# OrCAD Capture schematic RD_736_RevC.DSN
size Custom; title: DER-736_RevC; rev: A
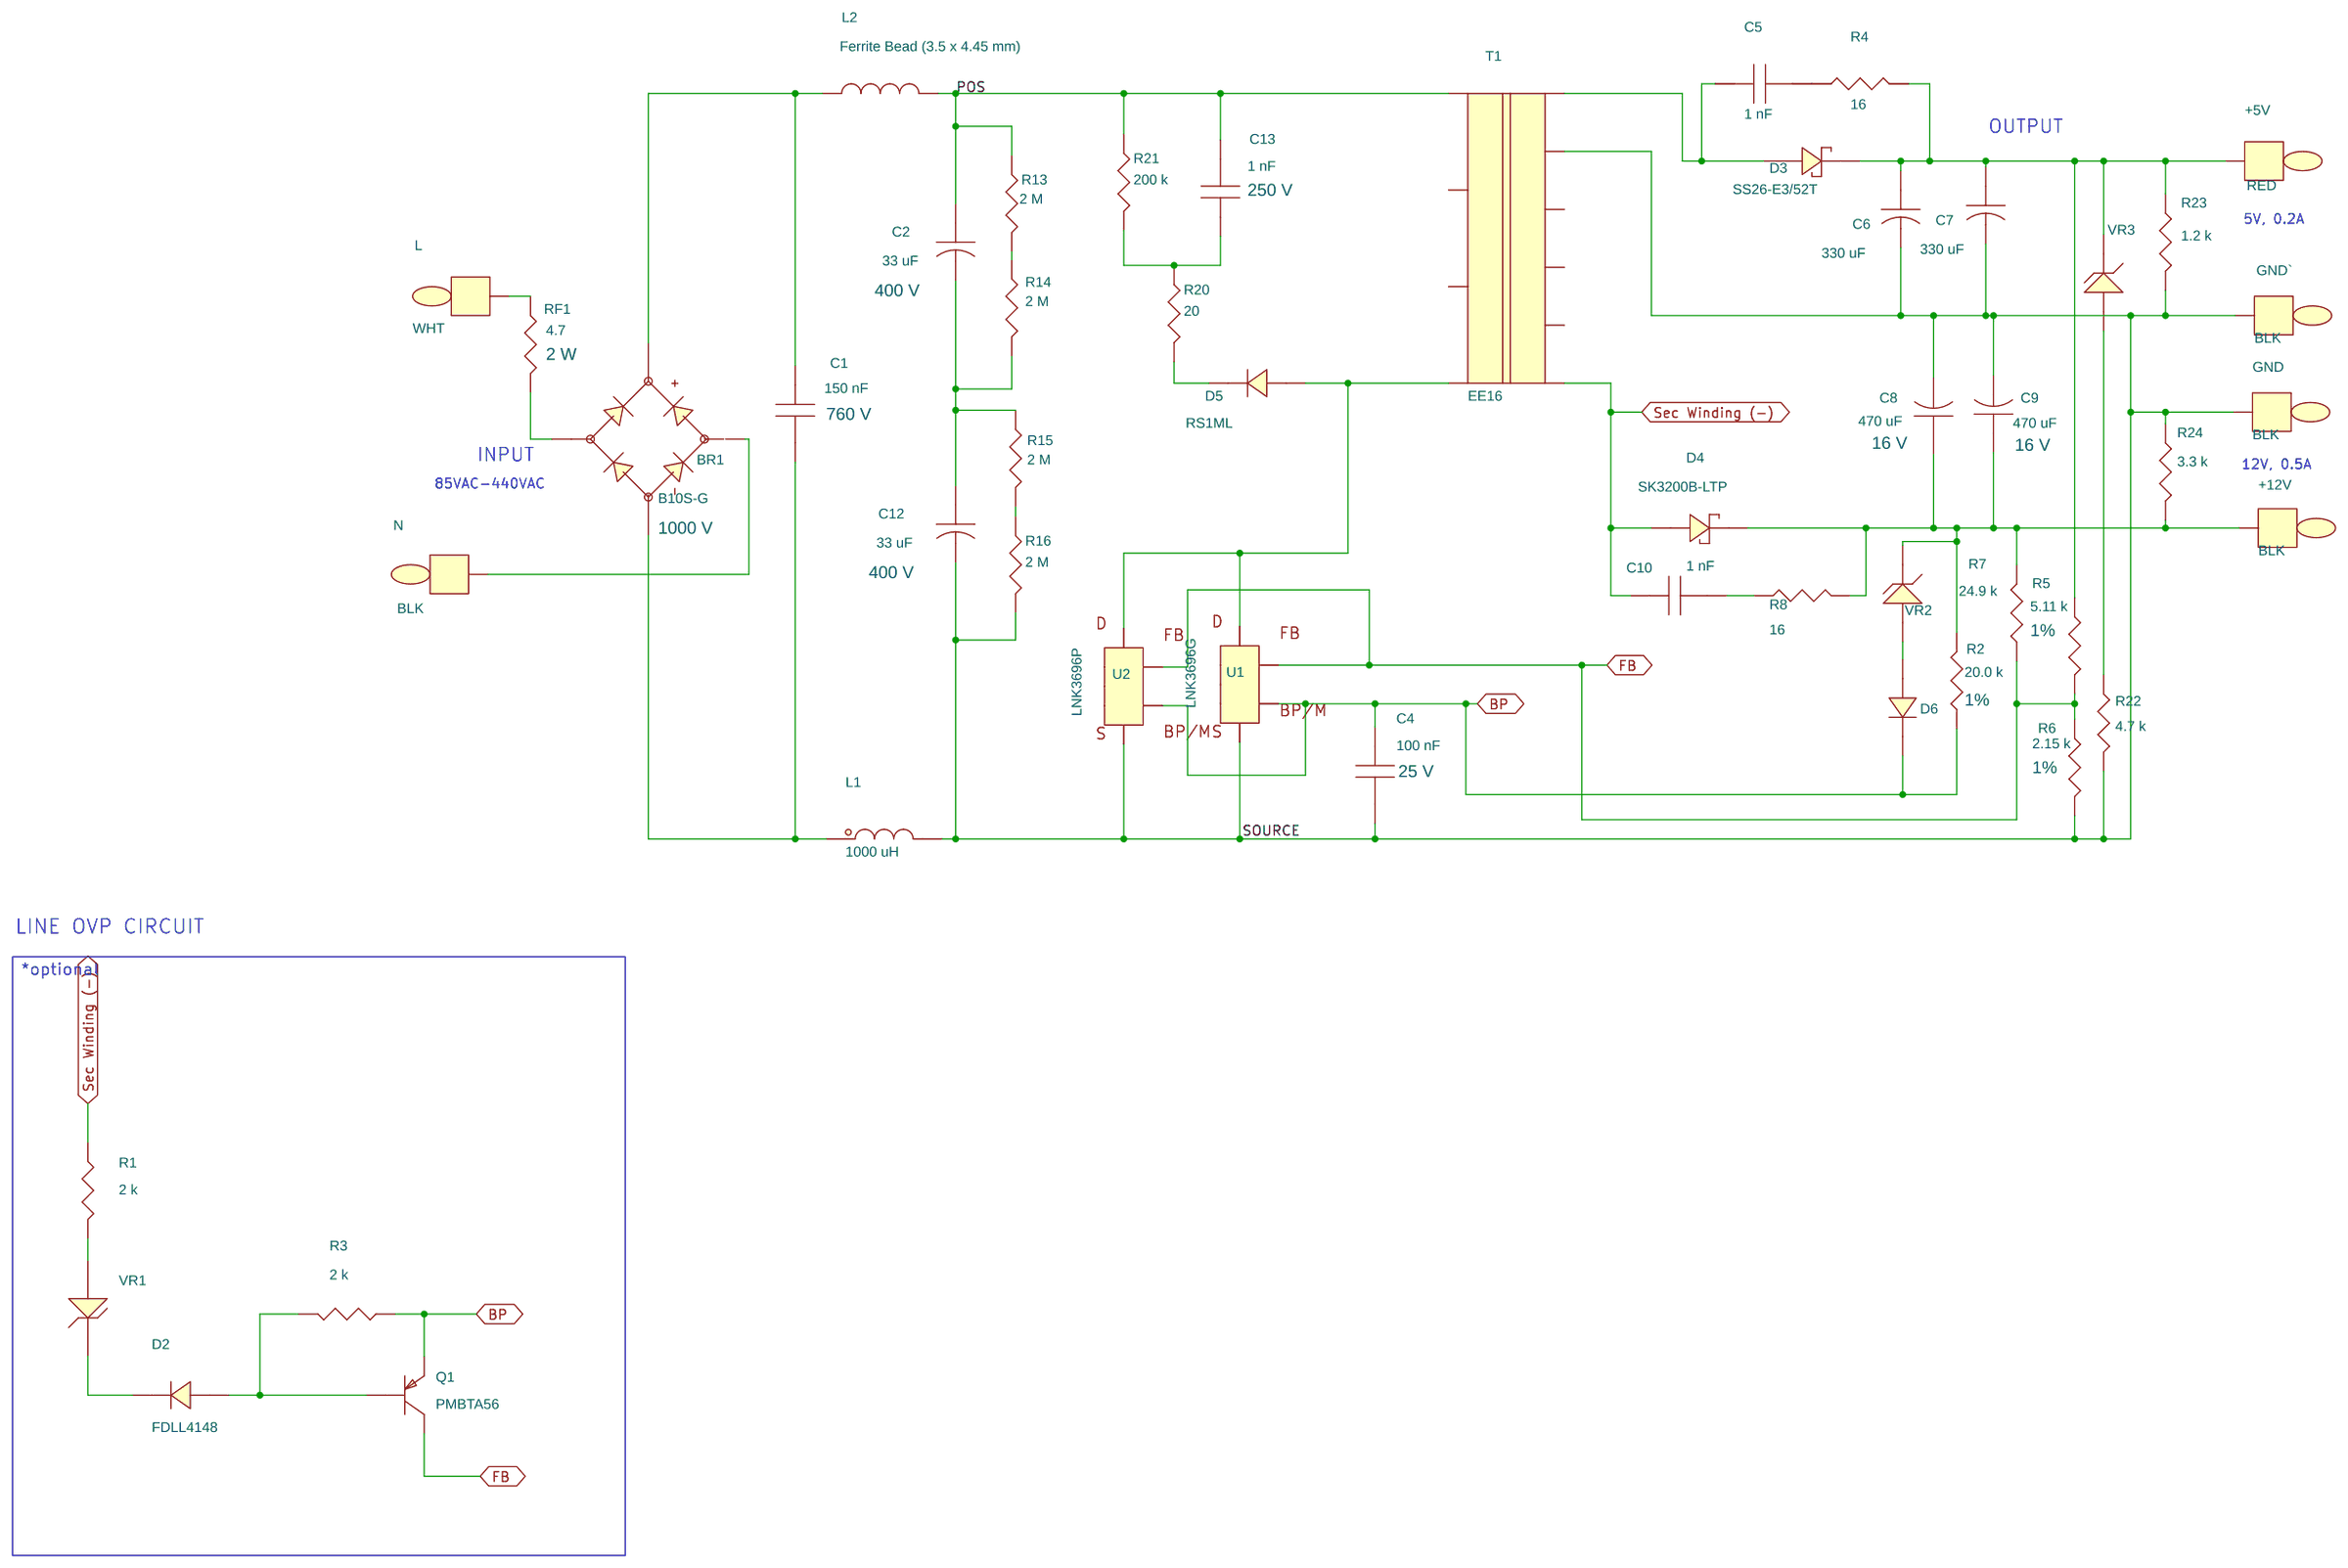
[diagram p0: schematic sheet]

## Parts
+5V  RED  [pitpkeystone100x100]
+12V  BLK  [pitpkeystone100x100]
BR1  B10S-G  [pismsoic4]
C1  150 nF  [pi_np_caprad709x276ls590d050]
C2  33 uF  [pipolcapclyd500ls200040]
C4  100 nF  [pismc1206]
C5  1 nF  [pismc0805]
C6  330 uF  [pipolcapclyd320ls140030]
C7  330 uF  [pipolcapclyd320ls140030]
C8  470 uF  [pipolcapcyld400ls200040]
C9  470 uF  [pipolcapcyld400ls200040]
C10  1 nF  [pismc0805]
C12  33 uF  [pipolcapclyd500ls200040]
C13  1 nF  [pismc0805]
D2  FDLL4148  [pismdminimelf]
D3  SS26-E3/52T  [pismdo214aa12]
D4  SK3200B-LTP  [pismsmb]
D5  RS1ML  [pi_sm_sod-123_12]
D6  FDLL4148  [pismdminimelf]
GND  BLK  [pitpkeystone100x100]
GND`  BLK  [pitpkeystone100x100]
L  WHT  [pitpkeystone125x125]
L1  1000 uH  [pi_choke_RLB9012_D2]
L2  Ferrite Bead (3.5 x 4.45 mm)  [pi12wresd180ls675d040]
N  BLK  [pitpkeystone125x125]
Q1  PMBTA56  [pismsot23123_1]
R1  2 k  [pismr1206]
R2  20.0 k  [pismr1206]
R3  2 k  [pismr0805]
R4  16  [pismr0805]
R5  5.11 k  [pismr0805]
R6  2.15 k  [pismr0603]
R7  24.9 k  [pismr0805]
R8  16  [pismr0805]
R13  2 M  [pismr1206]
R14  2 M  [pismr1206]
R15  2 M  [pismr1206]
R16  2 M  [pismr1206]
R20  20  [pismr1206]
R21  200 k  [pismr1206]
R22  4.7 k  [pismr0805]
R23  1.2 k  [pismr0805]
R24  3.3 k  [pismr0805]
RF1  4.7  [pi_2w_vresd145ls150d040]
T1  EE16  [pibobbinee1610p4x6]
U1  LNK3696G  [piicsmd8cshort5678]
U2  LNK3696P  [piicdip8cshort5678]
VR1  MMSZ5267BT1G  [pi_sm_sod-123_12]
VR2  MMSZ5242B-7-F  [pi_sm_sod-123_12]
VR3  MMSZ5234B-7-F  [pi_sm_sod-123_12]

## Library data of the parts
+5V = TESTPOINT: Part Number: 35-00080-00
+12V GND GND` = TESTPOINT: Part Number: 35-00079-00
BR1 = DIODE_BRIDGE_~~+-: ALT_SYMBOLS: pi_sm_soic4_slot; Disp_Voltage: 1000 V; FPLIST: pismsoic4,pi_sm_soic4_slot; Part Number: 15-00818-00
C1 = CAP_NP: Disp_Voltage: 760 V; Part Number: 20-01058-00; Voltage: 760 V
C2 C12 = CAP_POL: ALT_SYMBOLS: pipolcapclyd500ls200040800lh; COMPGROUP: 1; Disp_Voltage: 400 V; FPLIST: pipolcapclyd500ls200040,pipolcapclyd500ls200040800lh; PCB Editor PCBFP: pipolcapclyd320ls140030; Part Number: 20-00888-00; Voltage: 400 V
C4 = CAP_NP: Disp_Voltage: 25 V; Part Number: 20-08743-00; Voltage: 25 V
C5 = CAP_NP: COMPGROUP: 2; Disp_Voltage: 50 V; Part Number: 20-08750-00; Voltage: 50 V
C6 C7 = CAP_POL: ALT_SYMBOLS: pipolcapclyd320ls140030430h; COMPGROUP: 2; Disp_Voltage: 16 V; FPLIST: pipolcapclyd320ls140030,pipolcapclyd320ls140030430h; Part Number: 20-00014-00; Voltage: 16 V
C8 C9 = CAP_POL: ALT_SYMBOLS: pipolcapclyd400x530ls200030h; COMPGROUP: 2; Disp_Voltage: 16 V; FPLIST: pipolcapcyld400ls200040,pipolcapclyd400x530ls200030h; PCB Editor PCBFP: pipolcapclyd320ls140030; Part Number: 20-00017-00; Voltage: 16 V
C10 C13 = CAP_NP: Disp_Voltage: 250 V; Part Number: 20-00736-00; Voltage: 250 V
D2 D6 = DIODE: Part Number: 15-01318-00
D3 = DIODE_SCHOTTKY: ALT_SYMBOLS: pismdo214ac12; COMPGROUP: 2; FPLIST: pismdo214aa12,pismdo214ac12; Part Number: 15-00366-00
D4 = DIODE_SCHOTTKY: COMPGROUP: 2; Part Number: 15-00877-00
D5 = DIODE: Part Number: 15-01045-00
L = TESTPOINT: Part Number: 35-00044-00
L1 = INDUCTOR_DOT2: Part Number: 30-00363-00
L2 = INDUCTOR: ALT_SYMBOLS: pi12wvresd180ls150d040,pi12wvresd180ls200d040,pi12wvresd180ls250d040; COMPGROUP: 1; FPLIST: PI_1/2W_RES/D.180/LS.675/.040,PI_1/2W_VRES/D.180/LS150/.040,PI_1/2W_VRES/D.180/LS200/.040,PI_1/2W_VRES/D.180/LS250/.040; Part Number: 30-00143-00
N = TESTPOINT: Part Number: 35-00042-00
Q1 = PNP_BEC: Part Number: 55-00031-00
R1 = R: Disp_Tol: 1%; Part Number: 05-00222-00
R2 = R: Disp_Tol: 1%; PCB Editor PCBFP: pi14wvresd100ls100d030,pi14wvresd100ls200d030,pi14wresd100ls400d030,pi14wresd100ls500d030; Part Number: 05-00318-00
R3 = R: Part Number: 05-01526-00
R4 R8 = R: COMPGROUP: 2; Part Number: 05-01476-00
R5 = R: Disp_Tol: 1%; Part Number: 05-03374-00
R6 = R: Disp_Tol: 1%; Part Number: 05-01110-00
R7 = R: Disp_Tol: 1%; Part Number: 05-00722-00
R13-R16 = R: Part Number: 05-01428-00
R20 = R: Part Number: 05-01311-00
R21 = R: Part Number: 05-01407-00
R22 = R: Part Number: 05-01535-00
R23 = R: Part Number: 05-01521-00
R24 = R: Part Number: 05-01531-00
RF1 = RF: ALT_SYMBOLS: pi_2w_resd145ls455d040; Disp_Power: 2 W; FPLIST: pi_2w_vresd145ls150d040,pi_2w_resd145ls455d040; PCB Editor PCBFP: pi2wresd200ls725d040,pi2wresd200ls900d040,pi2wvresd200ls300d040,pi2wvresd200ls400d040,pi2wvresd180ls250d040,pi2wvresd180ls200d040; Part Number: 05-05552-00
T1 = BEE16_10P_4x6_GENERIC: Part Number: 25-00846-00
U1 = LNK3696_4: FPLIST: piicsmd8cshort5678ipc,piicsmd8cshort5678; Part Number: 10-01088-00
U2 = LNK3696_3: Part Number: 10-01089-00
VR1 = DIODE_ZENER: Part Number: 15-01171-00
VR2 = DIODE_ZENER: Part Number: 15-01090-00
VR3 = DIODE_ZENER: Part Number: 15-01083-00

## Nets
BP: C4.1 D6.1 Q1.2(EMITTER) R2.1 R3.1 U1.1(BP/M) U2.1(BP/M)
FB: Q1.3(COLLECTOR) R5.2 R6.1 R7.1 U1.2(FB) U2.2(FB)
POS: C2.1 C13.2 L2.1 R13.2 R21.2 T1.1
Sec Winding (-): C10.1 D4.2 R1.2 T1.5
SOURCE: C4.2 C6.2 C7.2 C8.2 C9.2 C12.2 GND.1 GND`.1 L1.1 R6.2 R16.1 R22.2 R23.2 R24.1 T1.9 U1.5(S) U2.5(S)
N113320: +5V.1 C6.1 C7.1 D3.1 R4.2 R5.1 R23.1 VR3.1
N173843: BR1.3 C1.1 L2.2
N175187: BR1.4 C1.2 L1.2
N2606021: R1.1 VR1.2
N2627623: C5.1 D3.2 T1.10
N2638033: L.1 RF1.1
N2638037: BR1.1 RF1.2
N2638056: BR1.2 N.1
N2642522: +12V.1 C8.1 C9.1 D4.1 R2.2 R7.2 R8.2 R24.2 VR2.1
N2645458: C10.2 R8.1
N2649083: C2.2 C12.1 R14.1 R15.2
N2650921: R13.1 R14.2
N2651642: R15.1 R16.2
N4163745: D5.2 T1.4 U1.4(D) U2.4(D)
N4175640: D5.1 R20.1
N4176694: C13.1 R20.2 R21.1
N4182640: R22.1 VR3.2
N4208688: D6.2 VR2.2
N4211492: D2.2 Q1.1(BASE) R3.2
N4211556: D2.1 VR1.1
N4235738: C5.2 R4.1

Not connected (* = marked no-connect by the designer): T1 2 3 6 7 8; U1 6(S6) 7(S7) 8(S8); U2 6(S6) 7(S7) 8(S8)

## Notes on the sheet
- OUTPUT
- 5V, 0.2A
- INPUT
- 12V, 0.5A
- 85VAC-440VAC
- LINE OVP CIRCUIT
- *optional
